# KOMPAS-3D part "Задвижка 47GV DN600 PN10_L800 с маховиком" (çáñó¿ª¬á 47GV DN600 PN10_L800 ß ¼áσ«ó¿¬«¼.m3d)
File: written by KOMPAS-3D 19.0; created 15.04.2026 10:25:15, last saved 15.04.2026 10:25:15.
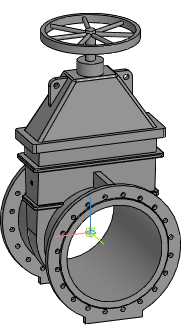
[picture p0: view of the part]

Document properties: Автор: Евгений; Полное имя файла: Z:\3.Личные\kachalov\3d для проектировщиков\2.1 Тип 47GV, 47GV.Z\Задвижка 47GV_DN40-DN600\stp_Задвижка 47GV\Задвижка 47GV DN600 PN10_L800 с маховиком.m3d

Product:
- Part/product: Задвижка 47GV DN600 PN10_L800 с маховиком

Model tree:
1. Операция без истории:1  (labels: Задвижка 47GV DN600 PN10_L800 с маховиком)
